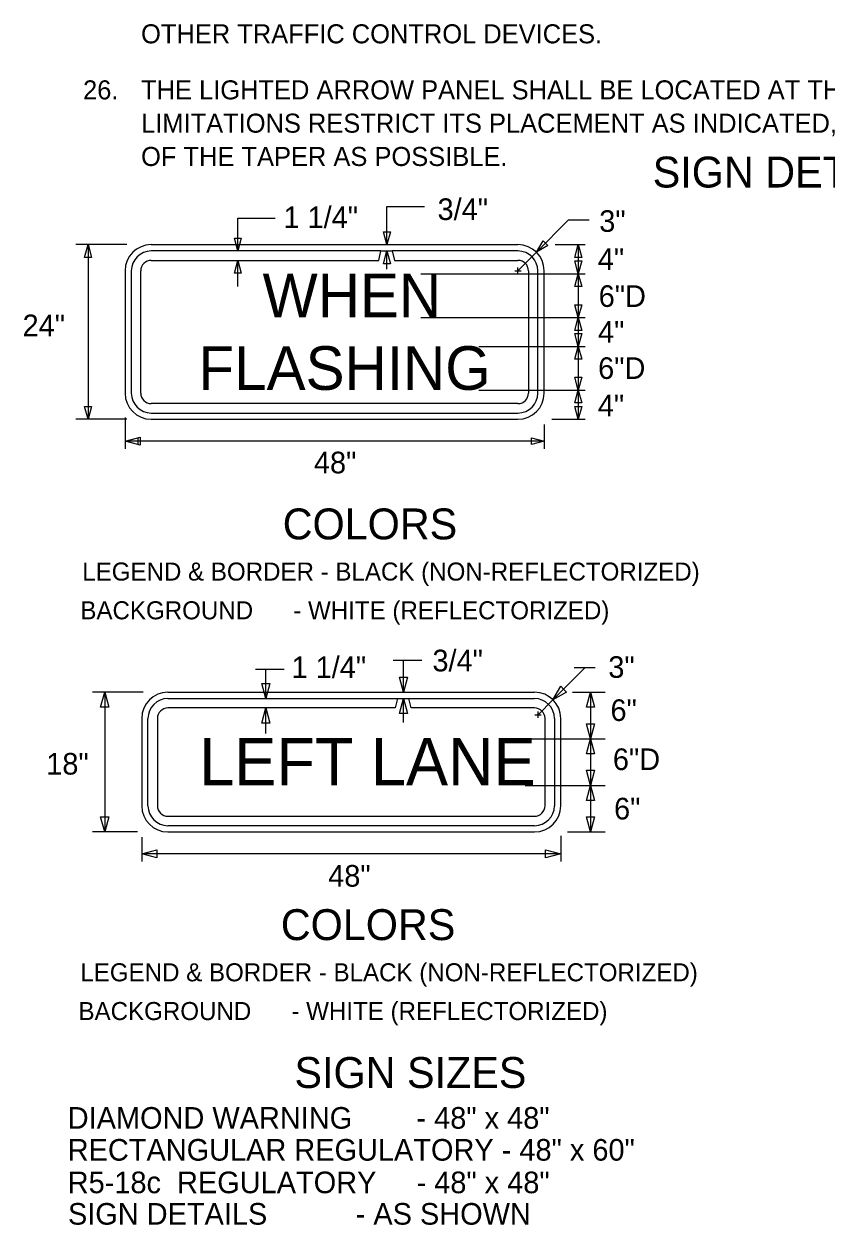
# Model space of a CAD drawing. Extents: x 15261 to 18126, y 1908 to 6555.
# Drawn here: x 17433.1 to 17744.9, y 2205.1 to 2671.6 of the extents above; entities that cross this region are included whole.
import ezdxf

# ---------------------------------------------------------------- set-up
doc = ezdxf.new("R2010")
doc.units = 0
for name, color, linetype in [('MT_SCRATCH_LEVEL_A', 7, 'Continuous'), ('TYPICAL_EX', 7, 'Continuous'), ('TYPICAL_TEXT_DIMEN_EX', 7, 'Continuous'), ('TYPICAL_TEXT_DIMEN_PR', 7, 'Continuous')]:
    doc.layers.add(name, color=color, linetype=linetype)

msp = doc.modelspace()

# ---------------------------------------------------------------- linework, layer by layer
at = {"layer": 'MT_SCRATCH_LEVEL_A'}
for p, q in [((17574.06, 2600.7), (17588.62, 2600.7)), ((17516.12, 2596.16), (17530.67, 2596.16)), ((17632.08, 2582.95), (17644.43, 2595.36)), ((17652.63, 2595.36), (17644.43, 2595.36)), ((17624.93, 2575.77), (17632.08, 2582.95)), ((17623.68, 2575.77), (17626.18, 2575.77)), ((17624.93, 2574.55), (17624.93, 2577.05)), ((17472.34, 2518.74), (17472.34, 2506.66)), ((17635.1, 2516.01), (17635.1, 2506.66)), ((17635.1, 2509.57), (17472.34, 2509.57)), ((17576.41, 2424.48), (17587.55, 2424.48)), ((17638.51, 2409.1), (17650.85, 2421.48)), ((17654.92, 2421.49), (17646.75, 2421.49)), ((17522.96, 2421.01), (17534.09, 2421.01)), ((17632.71, 2403.28), (17638.51, 2409.1)), ((17631.43, 2403.28), (17633.97, 2403.28)), ((17632.71, 2402.06), (17632.71, 2404.53)), ((17478.81, 2355.77), (17478.81, 2346.36)), ((17641.53, 2356.35), (17641.53, 2346.36)), ((17641.53, 2349.28), (17478.81, 2349.28))]:
    msp.add_line(p, q, dxfattribs=at)
at = {"layer": 'TYPICAL_EX'}
for p, q in [((17482.51, 2585.91), (17624.93, 2585.91)), ((17571.65, 2583.47), (17482.51, 2583.47)), ((17482.51, 2579.81), (17570.84, 2579.81)), ((17570.84, 2579.81), (17571.65, 2583.47)), ((17571.65, 2583.47), (17576.07, 2583.47)), ((17624.93, 2583.47), (17576.07, 2583.47)), ((17576.07, 2583.47), (17577.01, 2579.81)), ((17577.01, 2579.81), (17624.93, 2579.81)), ((17472.34, 2575.74), (17472.34, 2528.25)), ((17474.78, 2575.74), (17474.78, 2528.25)), ((17478.44, 2528.25), (17478.44, 2575.74)), ((17629, 2575.74), (17629, 2528.25)), ((17632.66, 2528.25), (17632.66, 2575.74)), ((17635.1, 2528.25), (17635.1, 2575.74)), ((17624.93, 2524.19), (17482.51, 2524.19)), ((17482.51, 2520.52), (17624.93, 2520.52)), ((17482.51, 2518.08), (17624.93, 2518.08)), ((17488.98, 2412.06), (17631.36, 2412.06)), ((17488.98, 2409.62), (17578.1, 2409.62)), ((17578.1, 2409.62), (17577.29, 2405.96)), ((17578.1, 2409.62), (17582.51, 2409.62)), ((17577.29, 2405.96), (17488.98, 2405.96)), ((17478.81, 2401.89), (17478.81, 2367.96)), ((17481.25, 2367.96), (17481.25, 2401.89)), ((17484.91, 2401.89), (17484.91, 2367.96)), ((17641.53, 2367.96), (17641.53, 2401.89)), ((17488.98, 2363.89), (17631.36, 2363.89)), ((17631.36, 2360.23), (17488.98, 2360.23)), ((17488.98, 2357.79), (17631.36, 2357.79))]:
    msp.add_line(p, q, dxfattribs=at)
for centre, radius, start, end in [((17482.51, 2575.74), 10.17, 90, 180), ((17624.93, 2575.74), 10.17, 0, 90), ((17482.51, 2575.74), 7.73, 90, 180), ((17482.51, 2575.74), 4.07, 90, 180), ((17624.93, 2575.74), 7.73, 0, 90), ((17624.93, 2575.74), 4.07, 0, 90), ((17482.51, 2528.25), 10.17, 180, 270), ((17482.51, 2528.25), 7.73, 180, 270), ((17482.51, 2528.25), 4.07, 180, 270), ((17624.93, 2528.25), 10.17, 270, 0), ((17624.93, 2528.25), 4.07, 270, 0), ((17624.93, 2528.25), 7.73, 270, 0), ((17488.98, 2401.89), 10.17, 90, 180), ((17631.36, 2401.89), 10.17, 0, 90), ((17488.98, 2401.89), 7.73, 90, 180), ((17488.98, 2401.89), 4.07, 90, 180), ((17488.98, 2367.96), 10.17, 180, 270), ((17488.98, 2367.96), 7.73, 180, 270), ((17488.98, 2367.96), 4.07, 180, 270), ((17631.36, 2367.96), 10.17, 270, 0), ((17631.36, 2367.96), 7.73, 270, 0), ((17631.36, 2367.96), 4.07, 270, 0)]:
    msp.add_arc(centre, radius, start, end, dxfattribs=at)
at = {"layer": 'TYPICAL_TEXT_DIMEN_PR'}
for p, q in [((17574.06, 2585.91), (17574.06, 2600.7)), ((17516.12, 2583.47), (17516.12, 2596.16)), ((17574.06, 2585.91), (17572.73, 2590.89)), ((17572.73, 2590.89), (17574.06, 2590.89)), ((17574.06, 2590.89), (17575.4, 2590.89)), ((17575.4, 2590.89), (17574.06, 2585.91)), ((17473, 2585.91), (17453.25, 2585.91)), ((17456.64, 2580.93), (17457.97, 2585.91)), ((17457.97, 2585.91), (17457.97, 2518.08)), ((17457.97, 2585.91), (17459.31, 2580.93)), ((17516.12, 2583.47), (17514.79, 2588.45)), ((17514.79, 2588.45), (17516.12, 2588.45)), ((17516.12, 2588.45), (17517.46, 2588.45)), ((17517.46, 2588.45), (17516.12, 2583.47)), ((17632.08, 2582.95), (17634.65, 2587.43)), ((17636.54, 2585.54), (17632.08, 2582.95)), ((17634.65, 2587.43), (17635.59, 2586.48)), ((17635.59, 2586.48), (17636.54, 2585.54)), ((17639.37, 2585.91), (17651.06, 2585.91)), ((17647.03, 2580.93), (17648.36, 2585.91)), ((17648.36, 2585.91), (17648.36, 2574.59)), ((17648.36, 2585.91), (17649.69, 2580.93)), ((17457.97, 2580.93), (17456.64, 2580.93)), ((17459.31, 2580.93), (17457.97, 2580.93)), ((17514.79, 2574.82), (17516.12, 2579.81)), ((17516.12, 2569.71), (17516.12, 2579.81)), ((17516.12, 2579.81), (17517.46, 2574.82)), ((17572.73, 2578.48), (17574.06, 2583.47)), ((17574.06, 2576.44), (17574.06, 2583.47)), ((17574.06, 2583.47), (17575.4, 2578.48)), ((17648.36, 2580.93), (17647.03, 2580.93)), ((17649.69, 2580.93), (17648.36, 2580.93)), ((17574.06, 2578.48), (17572.73, 2578.48)), ((17575.4, 2578.48), (17574.06, 2578.48)), ((17648.36, 2574.59), (17647.03, 2579.57)), ((17647.03, 2579.57), (17648.36, 2579.57)), ((17648.36, 2579.57), (17649.69, 2579.57)), ((17649.69, 2579.57), (17648.36, 2574.59)), ((17516.12, 2574.82), (17514.79, 2574.82)), ((17517.46, 2574.82), (17516.12, 2574.82)), ((17587.15, 2574.59), (17651.06, 2574.59)), ((17647.03, 2569.61), (17648.36, 2574.59)), ((17648.36, 2574.59), (17648.36, 2557.61)), ((17648.36, 2574.59), (17649.69, 2569.61)), ((17648.36, 2569.61), (17647.03, 2569.61)), ((17649.69, 2569.61), (17648.36, 2569.61)), ((17648.36, 2557.61), (17647.03, 2562.59)), ((17647.03, 2562.59), (17648.36, 2562.59)), ((17648.36, 2562.59), (17649.69, 2562.59)), ((17649.69, 2562.59), (17648.36, 2557.61)), ((17587.15, 2557.61), (17651.06, 2557.61)), ((17647.03, 2552.63), (17648.36, 2557.61)), ((17648.36, 2557.61), (17648.36, 2546.38)), ((17648.36, 2557.61), (17649.69, 2552.63)), ((17648.36, 2552.63), (17647.03, 2552.63)), ((17649.69, 2552.63), (17648.36, 2552.63)), ((17648.36, 2546.38), (17647.03, 2551.37)), ((17647.03, 2551.37), (17648.36, 2551.37)), ((17648.36, 2546.38), (17647.03, 2551.37)), ((17647.03, 2551.37), (17648.36, 2551.37)), ((17648.36, 2551.37), (17649.69, 2551.37)), ((17649.69, 2551.37), (17648.36, 2546.38)), ((17648.36, 2551.37), (17649.69, 2551.37)), ((17649.69, 2551.37), (17648.36, 2546.38)), ((17609.76, 2546.38), (17651.06, 2546.38)), ((17647.03, 2541.4), (17648.36, 2546.38)), ((17648.36, 2546.38), (17648.36, 2529.4)), ((17648.36, 2546.38), (17649.69, 2541.4)), ((17648.36, 2541.4), (17647.03, 2541.4)), ((17649.69, 2541.4), (17648.36, 2541.4)), ((17648.36, 2529.4), (17647.03, 2534.39)), ((17647.03, 2534.39), (17648.36, 2534.39)), ((17648.36, 2529.4), (17647.03, 2534.39)), ((17647.03, 2534.39), (17648.36, 2534.39)), ((17648.36, 2534.39), (17649.69, 2534.39)), ((17649.69, 2534.39), (17648.36, 2529.4)), ((17648.36, 2534.39), (17649.69, 2534.39)), ((17649.69, 2534.39), (17648.36, 2529.4)), ((17609.76, 2529.4), (17651.06, 2529.4)), ((17647.03, 2524.42), (17648.36, 2529.4)), ((17648.36, 2529.4), (17648.36, 2518.08)), ((17648.36, 2529.4), (17649.69, 2524.42)), ((17648.36, 2524.42), (17647.03, 2524.42)), ((17649.69, 2524.42), (17648.36, 2524.42)), ((17457.97, 2518.08), (17456.64, 2523.07)), ((17456.64, 2523.07), (17457.97, 2523.07)), ((17457.97, 2523.07), (17459.31, 2523.07)), ((17459.31, 2523.07), (17457.97, 2518.08)), ((17648.36, 2518.08), (17647.03, 2523.07)), ((17647.03, 2523.07), (17648.36, 2523.07)), ((17648.36, 2523.07), (17649.69, 2523.07)), ((17649.69, 2523.07), (17648.36, 2518.08)), ((17473, 2518.08), (17453.25, 2518.08)), ((17638.12, 2518.08), (17651.06, 2518.08)), ((17472.34, 2509.57), (17478.2, 2511.14)), ((17472.34, 2509.57), (17477.32, 2510.9)), ((17477.32, 2510.9), (17477.32, 2509.57)), ((17478.2, 2511.14), (17478.2, 2509.57)), ((17630.12, 2509.57), (17630.12, 2510.9)), ((17630.12, 2510.9), (17635.1, 2509.57)), ((17478.2, 2508), (17472.34, 2509.57)), ((17477.32, 2508.23), (17472.34, 2509.57)), ((17477.32, 2509.57), (17477.32, 2508.23)), ((17478.2, 2509.57), (17478.2, 2508)), ((17635.1, 2509.57), (17630.12, 2508.23)), ((17630.12, 2508.23), (17630.12, 2509.57)), ((17580.51, 2412.06), (17580.51, 2424.49)), ((17527.05, 2409.62), (17527.05, 2421.01)), ((17580.51, 2412.06), (17578.94, 2417.92)), ((17578.94, 2417.92), (17580.51, 2417.92)), ((17580.51, 2417.92), (17582.08, 2417.92)), ((17582.08, 2417.92), (17580.51, 2412.06)), ((17479.45, 2412.06), (17459.72, 2412.06)), ((17462.86, 2406.2), (17464.44, 2412.06)), ((17464.44, 2412.06), (17464.44, 2357.79)), ((17464.44, 2412.06), (17466.01, 2406.2)), ((17527.05, 2409.62), (17525.48, 2415.48)), ((17525.48, 2415.48), (17527.05, 2415.48)), ((17527.05, 2415.48), (17528.62, 2415.48)), ((17528.62, 2415.48), (17527.05, 2409.62)), ((17638.51, 2409.1), (17641.54, 2414.37)), ((17643.76, 2412.15), (17638.51, 2409.1)), ((17641.54, 2414.37), (17642.65, 2413.26)), ((17642.65, 2413.26), (17643.76, 2412.15)), ((17646.15, 2412.06), (17658.85, 2412.06)), ((17651.48, 2406.2), (17653.06, 2412.06)), ((17653.06, 2412.06), (17653.06, 2393.97)), ((17653.06, 2412.06), (17654.63, 2406.2)), ((17488.98, 2409.62), (17578.1, 2409.62)), ((17578.1, 2409.62), (17577.29, 2405.96)), ((17578.94, 2403.76), (17580.51, 2409.62)), ((17580.51, 2400.26), (17580.51, 2409.62)), ((17580.51, 2409.62), (17582.08, 2403.76)), ((17583.42, 2405.96), (17582.51, 2409.62)), ((17582.51, 2409.62), (17631.36, 2409.62)), ((17464.44, 2406.2), (17462.86, 2406.2)), ((17466.01, 2406.2), (17464.44, 2406.2)), ((17577.29, 2405.96), (17488.98, 2405.96)), ((17525.48, 2400.1), (17527.05, 2405.96)), ((17527.05, 2395.97), (17527.05, 2405.96)), ((17527.05, 2405.96), (17528.62, 2400.1)), ((17580.51, 2403.76), (17578.94, 2403.76)), ((17582.08, 2403.76), (17580.51, 2403.76)), ((17631.36, 2405.96), (17583.42, 2405.96)), ((17653.06, 2406.2), (17651.48, 2406.2)), ((17654.63, 2406.2), (17653.06, 2406.2)), ((17481.25, 2367.96), (17481.25, 2401.89)), ((17484.91, 2401.89), (17484.91, 2367.96)), ((17527.05, 2400.1), (17525.48, 2400.1)), ((17528.62, 2400.1), (17527.05, 2400.1)), ((17635.43, 2367.96), (17635.43, 2401.89)), ((17639.09, 2401.89), (17639.09, 2367.96)), ((17653.06, 2393.97), (17651.48, 2399.83)), ((17651.48, 2399.83), (17653.06, 2399.83)), ((17653.06, 2399.83), (17654.63, 2399.83)), ((17654.63, 2399.83), (17653.06, 2393.97)), ((17627.72, 2393.97), (17658.85, 2393.97)), ((17651.48, 2388.11), (17653.06, 2393.97)), ((17653.06, 2393.97), (17653.06, 2375.88)), ((17653.06, 2393.97), (17654.63, 2388.11)), ((17653.06, 2388.11), (17651.48, 2388.11)), ((17654.63, 2388.11), (17653.06, 2388.11)), ((17653.06, 2375.88), (17651.48, 2381.74)), ((17651.48, 2381.74), (17653.06, 2381.74)), ((17653.06, 2381.74), (17654.63, 2381.74)), ((17654.63, 2381.74), (17653.06, 2375.88)), ((17627.72, 2375.88), (17658.85, 2375.88)), ((17651.48, 2370.01), (17653.06, 2375.88)), ((17653.06, 2375.88), (17653.06, 2357.79)), ((17653.06, 2375.88), (17654.63, 2370.01)), ((17653.06, 2370.01), (17651.48, 2370.01)), ((17654.63, 2370.01), (17653.06, 2370.01)), ((17464.44, 2357.79), (17462.86, 2363.65)), ((17462.86, 2363.65), (17464.44, 2363.65)), ((17464.44, 2363.65), (17466.01, 2363.65)), ((17466.01, 2363.65), (17464.44, 2357.79)), ((17488.98, 2363.89), (17631.36, 2363.89)), ((17653.06, 2357.79), (17651.48, 2363.65)), ((17651.48, 2363.65), (17653.06, 2363.65)), ((17653.06, 2363.65), (17654.63, 2363.65)), ((17654.63, 2363.65), (17653.06, 2357.79)), ((17477.18, 2357.79), (17459.72, 2357.79)), ((17631.36, 2360.23), (17488.98, 2360.23)), ((17644.15, 2357.79), (17658.85, 2357.79)), ((17478.81, 2349.28), (17484.67, 2350.85)), ((17484.67, 2347.71), (17478.81, 2349.28)), ((17484.67, 2350.85), (17484.67, 2349.28)), ((17484.67, 2349.28), (17484.67, 2347.71)), ((17635.67, 2349.28), (17635.67, 2350.85)), ((17635.67, 2350.85), (17641.53, 2349.28)), ((17641.53, 2349.28), (17635.67, 2347.71)), ((17635.67, 2347.71), (17635.67, 2349.28))]:
    msp.add_line(p, q, dxfattribs=at)
for centre, radius, start, end in [((17488.98, 2401.89), 7.73, 90, 180), ((17631.36, 2401.89), 7.73, 0, 90), ((17488.98, 2401.89), 4.07, 90, 180), ((17631.36, 2401.89), 4.07, 0, 90), ((17488.98, 2367.96), 7.73, 180, 270), ((17488.98, 2367.96), 4.07, 180, 270), ((17631.36, 2367.96), 4.07, 270, 0), ((17631.36, 2367.96), 7.73, 270, 0)]:
    msp.add_arc(centre, radius, start, end, dxfattribs=at)

# ---------------------------------------------------------------- texts
at = {"layer": 'TYPICAL_TEXT_DIMEN_EX'}
for s, height, p in [('WHEN   ', 16.968, (17525.76, 2557.7)), ('FLASHING', 16.968, (17500.85, 2529.51)), ('LEFT LANE', 18.308, (17501.17, 2375.94))]:
    msp.add_text(s, height=height, dxfattribs=at).set_placement(p)
at = {"layer": 'TYPICAL_TEXT_DIMEN_PR'}
for s, height, p in [('OTHER TRAFFIC CONTROL DEVICES.', 7.392, (17478.58, 2664.11)), ('26.', 7.392, (17456.04, 2642.34)), ('THE LIGHTED ARROW PANEL SHALL BE LOCATED AT THE BEGINNING OF THE TAPER AS SHOWN.  WHEN PHYSICAL', 7.392, (17478.58, 2642.34)), ('LIMITATIONS RESTRICT ITS PLACEMENT AS INDICATED, THEN IT SHALL BE PLACED AS CLOSE TO THE BEGINNING', 7.392, (17478.58, 2629.4)), ('OF THE TAPER AS POSSIBLE.', 7.392, (17478.58, 2616.47)), ('SIGN DETAILS', 12, (17677.25, 2608.11)), ('3/4"', 8.4, (17593.7, 2595.48)), ('1 1/4"', 8.4, (17533.85, 2592.34)), ('3"', 8.4, (17656.49, 2590.88)), ('4"', 8.4, (17655.93, 2576.11)), ('6"D', 8.4, (17656.28, 2561.73)), ('24"', 8.4, (17432.56, 2550.36)), ('4"', 8.4, (17656.02, 2547.85)), ('6"D', 8.4, (17656.05, 2533.76)), ('4"', 8.4, (17655.93, 2519.23)), ('48"', 8.4, (17545.69, 2497.08)), ('COLORS', 12, (17533.57, 2471.44)), ('LEGEND & BORDER - BLACK (NON-REFLECTORIZED)', 7, (17455.73, 2455.44)), ('BACKGROUND      - WHITE (REFLECTORIZED)', 7, (17455, 2440.39)), ('1 1/4"', 8.4, (17537, 2417.59)), ('3/4"', 8.4, (17591.71, 2420.17)), ('3"', 8.4, (17660.01, 2417.65)), ('6"', 8.4, (17660.85, 2400.9)), ('18"', 8.4, (17441.76, 2380.08)), ('6"D', 8.4, (17661.78, 2381.84)), ('6"', 8.4, (17662.24, 2362.66)), ('48"', 8.4, (17551.23, 2336.55)), ('COLORS', 12, (17532.84, 2315.79)), ('LEGEND & BORDER - BLACK (NON-REFLECTORIZED)', 7, (17455, 2299.78)), ('BACKGROUND      - WHITE (REFLECTORIZED)', 7, (17454.27, 2284.73)), ('SIGN SIZES', 12, (17538.14, 2258.35)), ('DIAMOND WARNING        - 48" x 48"', 8.4, (17450.1, 2242.53)), ('RECTANGULAR REGULATORY - 48" x 60"', 8.4, (17450.1, 2230.12)), ('R5-18c  REGULATORY     - 48" x 48"', 8.4, (17450.1, 2217.47)), ('SIGN DETAILS           - AS SHOWN', 8.4, (17450.18, 2205.25))]:
    msp.add_text(s, height=height, dxfattribs=at).set_placement(p)

doc.saveas('drawing.dxf')
